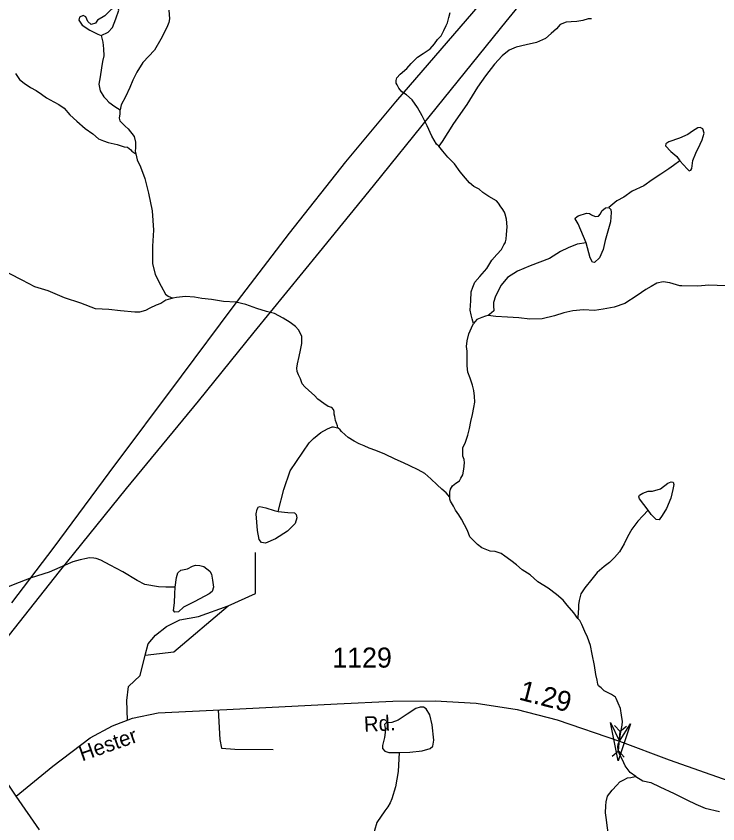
# Model space of a CAD drawing. Extents: x 2056842 to 2160602, y 826753 to 1016856.
# Drawn here: x 2087343 to 2091724, y 880850 to 885889 of the extents above; entities that cross this region are included whole.
import ezdxf

# ---------------------------------------------------------------- set-up
doc = ezdxf.new("R2010")
doc.units = 0
for name, color, linetype in [('Exist Hydrographic Creek Single Shore', 7, 'Continuous'), ('Exist Hydrographic Misc Water Feature', 7, 'Continuous'), ('Exist Road Non-System Type 51', 7, 'Continuous'), ('Exist Road Primary Interstate Divided Center Attributed', 7, 'Continuous'), ('Exist Road Secondary Mileage Hundredths English Label', 7, 'Continuous'), ('Exist Road Secondary Structure Pipe Attributed CELL', 7, 'Continuous'), ('Exist Road Secondary Structure Pipe CELL', 7, 'Continuous'), ('Exist Road Secondary Type 51 Attributed', 7, 'Continuous'), ('Exist Road Secondary Type 51 Label', 7, 'Continuous'), ('Exist Road Secondary Type 51 Number Label', 7, 'Continuous')]:
    doc.layers.add(name, color=color, linetype=linetype)

msp = doc.modelspace()

# ---------------------------------------------------------------- linework, layer by layer
at = {"layer": 'Exist Hydrographic Creek Single Shore'}
for points in [[(2088296.1, 885925.2), (2088300.2, 885873), (2088296.1, 885849.3), (2088288.1, 885829.4), (2088268.3, 885789), (2088246.5, 885745.2), (2088206.7, 885677), (2088133.3, 885600.5), (2088095.4, 885538.4), (2088071.6, 885490.5), (2088051.5, 885444.4), (2088025.7, 885386.3), (2087997.8, 885336.2), (2087991.6, 885304.2)], [(2089982.1, 885078.3), (2089966.3, 885090.4), (2089938.1, 885140.2), (2089908, 885204.1), (2089877.7, 885266.1), (2089847.7, 885319.9), (2089815.5, 885365.8), (2089779.4, 885397.8), (2089751.3, 885417.7), (2089731.1, 885439.4), (2089721, 885459.7), (2089715, 885471.6), (2089715, 885487.4), (2089718.9, 885503.7), (2089740.8, 885527.5), (2089780.8, 885561.8), (2089808.7, 885593.7), (2089848.6, 885633.9), (2089884.5, 885656.1), (2089928.4, 885684.1), (2089954.3, 885716.4), (2089972.3, 885742.2), (2089996, 885766.4), (2090012.1, 885798.5), (2090027.9, 885830.3), (2090035.8, 885846.6), (2090043.7, 885880.5), (2090051.6, 885912.5)], [(2087874.3, 885768.4), (2087884.8, 885725.8), (2087886.9, 885685.7), (2087889.1, 885642), (2087881.3, 885605.8), (2087875, 885565.7), (2087867.6, 885510), (2087859.4, 885463.8), (2087867.8, 885422), (2087889.7, 885385.8), (2087903.9, 885371.8), (2087921.9, 885352.1), (2087958, 885324.3), (2087991.6, 885304.2)], [(2087339.2, 885530.1), (2087363.4, 885494.4), (2087391.7, 885470.3), (2087431.6, 885444.7), (2087467.7, 885424.6), (2087499.9, 885402.7), (2087531.9, 885378.7), (2087577.6, 885354.8), (2087610, 885336.9), (2087642.2, 885315.3), (2087678.1, 885273.4), (2087722.4, 885233.4), (2087774.3, 885187.4), (2087820.4, 885153.7), (2087856.7, 885123.8), (2087888.5, 885110.1), (2087916.6, 885100.1), (2087972.8, 885088.4), (2088016.7, 885074.4), (2088037, 885070.5), (2088058.9, 885054.6), (2088064.8, 885046.4), (2088088.8, 885030.5)], [(2087991.6, 885304.2), (2087990.2, 885300.4), (2087989.8, 885280.1), (2087986.1, 885252.3), (2087990.2, 885236.3), (2088004.1, 885220.3), (2088022.4, 885202.6), (2088042.3, 885186.6), (2088078.4, 885138.5), (2088088.6, 885102.4), (2088088.6, 885082.5), (2088088.6, 885066.7), (2088084.7, 885046.6), (2088088.8, 885030.5)], [(2090197.8, 883971.3), (2090189.5, 884001), (2090183.5, 884025.1), (2090177.5, 884055.1), (2090181.4, 884113.1), (2090183.2, 884169.2), (2090192.9, 884197.2), (2090207, 884229), (2090238.6, 884265.1), (2090280.7, 884315.4), (2090312.6, 884365.6), (2090344.5, 884401.7), (2090372.4, 884433.6), (2090388.1, 884461.9), (2090396.2, 884473.8), (2090398, 884481.7), (2090401.9, 884497.7), (2090403.8, 884525.8), (2090407.8, 884573.7), (2090403.5, 884621.7), (2090395.6, 884653.7), (2090391.6, 884665.9), (2090377.4, 884689.8), (2090369.4, 884699.8), (2090353.4, 884721.5), (2090341.3, 884737.5), (2090293.2, 884763.4), (2090257, 884789.4), (2090233.2, 884809.3), (2090201, 884827), (2090172.9, 884848.9), (2090149, 884878.9), (2090114.6, 884916.7), (2090078.6, 884966.7), (2090038.4, 885008.5), (2090006.4, 885046.6), (2089982.1, 885078.3)], [(2088088.8, 885030.5), (2088098.7, 884992.6), (2088119, 884948.9), (2088145.2, 884876.7), (2088169.6, 884785), (2088192, 884674.9), (2088200.2, 884553.2), (2088194.6, 884452.9), (2088193.2, 884345.2), (2088211.3, 884277.2), (2088247.1, 884205.1), (2088275.6, 884153.3), (2088291.8, 884141.1), (2088321.8, 884129.3)], [(2090902.2, 884475.4), (2090844.3, 884467.1), (2090788.3, 884443.2), (2090740.6, 884420.8), (2090672.5, 884376.8), (2090552.9, 884330.4), (2090472.8, 884298.3), (2090410.8, 884258.2), (2090370.9, 884209.8), (2090335.4, 884141.8), (2090323.7, 884101.7), (2090323.7, 884081.9), (2090325.5, 884050), (2090309.5, 884037.8), (2090289.5, 884021.8)], [(2088321.3, 884129.2), (2088277.4, 884117), (2088245.5, 884097), (2088217.7, 884085.1), (2088177.6, 884066.9), (2088149.8, 884052.7), (2088111.8, 884042.7), (2088083.6, 884042.6), (2087993.9, 884050.3), (2087921.8, 884058.1), (2087837.6, 884063.7), (2087745.5, 884097.5), (2087643.5, 884131.1), (2087543.3, 884174.8), (2087459.2, 884200.5), (2087379.3, 884242.2), (2087303.1, 884282.2), (2087247.2, 884307.9), (2087207.1, 884323.8)], [(2091771, 884206.2), (2091667, 884209.8), (2091598.7, 884203.4), (2091498.9, 884205.3), (2091487, 884205.4), (2091423.2, 884225.3), (2091382.8, 884230.9), (2091342.8, 884222.8), (2091307.1, 884202.6), (2091274.9, 884182.7), (2091219.2, 884146.5), (2091143.3, 884096.4), (2091075.4, 884072.2), (2091007.5, 884059.8), (2090953.6, 884051.7), (2090885.3, 884055.6), (2090817.5, 884051.3), (2090761.5, 884037), (2090703.7, 884019), (2090625.9, 884000.8), (2090549.5, 883998.6), (2090481.4, 884006), (2090409.4, 884010.1), (2090337.8, 884015.6), (2090289.5, 884021.8)], [(2089351.9, 883320.8), (2089347.9, 883332.7), (2089335.8, 883366.7), (2089331.7, 883390.4), (2089327.4, 883406.6), (2089327.4, 883422.7), (2089323.4, 883434.5), (2089313.5, 883446.6), (2089291.3, 883454.2), (2089263.5, 883472.2), (2089225.3, 883498.3), (2089205.1, 883522), (2089169.1, 883553.9), (2089145.2, 883576), (2089128.9, 883595.7), (2089117.1, 883625.8), (2089104.8, 883651.7), (2089096.7, 883671.9), (2089094.8, 883691.6), (2089098.7, 883719.7), (2089110.4, 883765.8), (2089118.5, 883805.9), (2089126.2, 883845.8), (2089126.1, 883889.8), (2089118, 883909.6), (2089106, 883931.9), (2089087.7, 883953.6), (2089053.8, 883977.6), (2089009.7, 884005.4), (2088955.5, 884033.4), (2088905.6, 884047.2), (2088845.6, 884064.9), (2088777.6, 884090.6), (2088713.5, 884104.4), (2088637.5, 884108.2), (2088561.3, 884122), (2088501.4, 884127.8), (2088455.3, 884135.6), (2088399.3, 884139.4), (2088343.4, 884133.3), (2088321.3, 884129.2)], [(2090289.5, 884021.8), (2090273.5, 884017.7), (2090250.1, 884009.5), (2090217.9, 883997.3), (2090197.8, 883971.5)], [(2090051, 882887), (2090050.9, 882898.8), (2090051, 882918.8), (2090055, 882938.7), (2090066.9, 882958.8), (2090086.9, 882974.8), (2090110.9, 882989.1), (2090118.8, 883007), (2090130.7, 883027.1), (2090136.7, 883063), (2090142.4, 883103), (2090140.2, 883123), (2090132.4, 883143.2), (2090132.3, 883171.1), (2090132.2, 883195), (2090148, 883231.1), (2090161.7, 883275.1), (2090173.7, 883315.3), (2090181.5, 883359.1), (2090191.6, 883403.2), (2090199.4, 883447.3), (2090205.4, 883481.3), (2090205.1, 883517.4), (2090200.9, 883553.2), (2090192.8, 883587.2), (2090176.6, 883631.2), (2090162.6, 883667.2), (2090158.5, 883707), (2090158.4, 883747), (2090158.2, 883787.1), (2090158.1, 883799.2), (2090154.1, 883827.2), (2090158.1, 883863.2), (2090167.9, 883907), (2090185.7, 883945), (2090197.8, 883971.3)], [(2090051, 882887), (2090027, 882914.7), (2090000.9, 882938.5), (2089970.9, 882964.4), (2089930.7, 883002.3), (2089894.6, 883036.2), (2089852.7, 883058.1), (2089800.5, 883084.1), (2089760.5, 883102), (2089708.5, 883125.7), (2089644.4, 883155.6), (2089588.2, 883179.4), (2089546.1, 883193.4), (2089516.2, 883207.1), (2089484, 883220.9), (2089452.2, 883237), (2089416, 883260.7), (2089395.9, 883276.9), (2089374, 883296.7), (2089365.8, 883308.7), (2089351.9, 883320.8)], [(2090849.4, 882131.6), (2090825.2, 882165.2), (2090783.2, 882213.3), (2090756.9, 882245), (2090717, 882281), (2090664.7, 882320.8), (2090600.5, 882360.5), (2090552.5, 882402.5), (2090502.3, 882434.4), (2090466.2, 882466.3), (2090430.3, 882492), (2090394.2, 882519.9), (2090370.2, 882535.9), (2090334, 882547.8), (2090302, 882551.7), (2090250.2, 882571.5), (2090222.1, 882593.4), (2090175.8, 882639.3), (2090159.9, 882679.3), (2090123.6, 882750.9), (2090105.5, 882776.9), (2090085.4, 882806.9), (2090073.1, 882831.1), (2090055.1, 882862.9), (2090051.1, 882874.8), (2090051, 882887)], [(2088335.3, 882326.4), (2088276.6, 882326.4), (2088230.4, 882327.6), (2088145.2, 882343), (2088099.1, 882367), (2088008.9, 882422.5), (2087928.9, 882464.3), (2087870.9, 882494.1), (2087842.8, 882506.1), (2087827, 882508.2), (2087798.7, 882510), (2087782.7, 882505.9), (2087742.9, 882495.8), (2087696.6, 882483.7), (2087649, 882463.3), (2087549.1, 882419.2), (2087437.2, 882385), (2087361.3, 882356.3), (2087281.3, 882324.2)], [(2091212.2, 881144.6), (2091176.3, 881170.6), (2091146, 881212.6), (2091128.1, 881248.4), (2091110.1, 881284.2), (2091101.8, 881310.3), (2091099.2, 881329.6), (2091101.8, 881347.1), (2091108.6, 881364.6), (2091116.7, 881410.4), (2091127.3, 881464.3), (2091127.5, 881488.3), (2091123, 881528.4), (2091115, 881568.3), (2091100.9, 881602.4), (2091088.8, 881632.1), (2091085, 881640.1), (2091058.8, 881656.1), (2091014.6, 881679.9), (2090994.7, 881698.1), (2090978.5, 881709.9), (2090974.5, 881721.8), (2090970.7, 881745.8), (2090962.6, 881781.7), (2090954.2, 881837.7), (2090939.9, 881907.9), (2090927.9, 881961.6), (2090909.6, 882013.5), (2090893.6, 882049.6), (2090873.6, 882093.7), (2090861.3, 882117.5), (2090849.4, 882131.6)], [(2089734.8, 881295.2), (2089727.3, 881175.2), (2089711, 881079.9), (2089688.5, 881004.9), (2089678.5, 880981.2), (2089663.5, 880954.9), (2089645.4, 880929.9), (2089593.6, 880858.7), (2089579.8, 880807.4), (2089573.6, 880778.6), (2089568.3, 880749.7), (2089547.8, 880721.6), (2089502.1, 880671.6), (2089388.5, 880607.2), (2089350.3, 880587.1), (2089314.8, 880575.1), (2089278.8, 880562.6), (2089202.9, 880538.4), (2089142.8, 880512.3), (2088981.3, 880458.8)], [(2091003.6, 880736.2), (2091015.8, 880752), (2091021.7, 880770.3), (2091029.5, 880782.2), (2091037.6, 880794.2), (2091037.3, 880810.3), (2091033.3, 880838.3), (2091029.1, 880874.1), (2091021.2, 880918.2), (2091025, 880962.1), (2091026.8, 880986), (2091034.8, 881022), (2091064.8, 881060.1), (2091092.7, 881090.3), (2091112.5, 881112.2), (2091136.3, 881124.6), (2091160.5, 881136.5), (2091180.3, 881138.7), (2091208.3, 881144.7), (2091212.2, 881144.6)], [(2091212.2, 881144.6), (2091256.3, 881118.8), (2091304.6, 881107), (2091360.5, 881081.2), (2091450.6, 881039.3), (2091530.8, 880999.6), (2091587, 880971.9), (2091644.9, 880948), (2091733, 880926.2)]]:
    msp.add_lwpolyline(points, dxfattribs=at)
at = {"layer": 'Exist Hydrographic Misc Water Feature'}
for points in [[(2087874.3, 885768.4), (2087918.1, 885788.4), (2087944.3, 885818.4), (2087964.3, 885872.2), (2087983, 885927.2), (2087974.3, 885953.5), (2087955.5, 885954.7), (2087938.1, 885932.2), (2087896.8, 885891), (2087850.6, 885864.7), (2087838.1, 885844.7), (2087810.6, 885836), (2087790.6, 885856), (2087778.1, 885884.7), (2087760.6, 885892.2), (2087738.1, 885883.5), (2087733.1, 885863.5), (2087754.4, 885833.5), (2087803.1, 885802.2), (2087853.1, 885775.9), (2087874.3, 885768.4)], [(2090934.3, 885872.5), (2090913.6, 885871.6), (2090880.2, 885861.3), (2090843.7, 885855), (2090807.8, 885853.2), (2090776, 885850.7), (2090740, 885836.7), (2090716.2, 885810.6), (2090684, 885780.7), (2090648.5, 885748.7), (2090590.5, 885724.2), (2090526.5, 885710), (2090464.2, 885695.9), (2090420.5, 885675.7), (2090376.6, 885641.8), (2090328.8, 885589.4), (2090273.1, 885517.5), (2090223.2, 885445.1), (2090155.4, 885337), (2090074.1, 885218.6), (2090002.4, 885106.5), (2089982.3, 885078.7)], [(2091486.3, 884985.4), (2091531.6, 884936.1), (2091544.1, 884924.8), (2091554.1, 884928.6), (2091561.6, 884938.6), (2091566.6, 884987.3), (2091585.3, 885034.8), (2091614, 885091.1), (2091626.5, 885117.3), (2091639, 885158.6), (2091629, 885186.1), (2091614, 885194.9), (2091597.8, 885191.1), (2091565.3, 885172.3), (2091535.3, 885151.1), (2091484.1, 885127.3), (2091416.6, 885104.8), (2091399.1, 885092.3), (2091396.6, 885079.8), (2091430.4, 885044.8), (2091466.6, 885013.6), (2091486.3, 884985.4)], [(2091486.3, 884985.4), (2091446.8, 884956.9), (2091416.6, 884937.1), (2091366.8, 884902.9), (2091312.9, 884866.9), (2091260.8, 884830.5), (2091189.2, 884796.4), (2091137.3, 884760), (2091093, 884736.7), (2091043, 884694.1)], [(2090902.2, 884475.4), (2090851.9, 884592.9), (2090833.1, 884624.1), (2090834.4, 884631.6), (2090850.6, 884642.9), (2090904.3, 884660.4), (2090923.1, 884657.9), (2090934.3, 884649.1), (2090958.1, 884637.9), (2090978, 884641.6), (2090990.5, 884655.4), (2090999.3, 884674.1), (2091021.8, 884692.9), (2091043, 884694.1)], [(2091043, 884694.1), (2091055.5, 884682.9), (2091058, 884662.9), (2091053, 884606.6), (2091020.5, 884489.1), (2091008, 884432.9), (2090984.3, 884381.6), (2090953.1, 884351.6), (2090940.6, 884354.1), (2090925.6, 884380.3), (2090902.2, 884475.4)], [(2088977.6, 882799.3), (2089013.9, 882935.6), (2089053.8, 883053.1), (2089172.3, 883226.1), (2089200, 883254.4), (2089245.9, 883290.5), (2089286.1, 883314.3), (2089315.7, 883326.5), (2089323.9, 883326.5), (2089340.3, 883322.9), (2089351.8, 883320.7)], [(2091287.6, 882806.8), (2091234.2, 882876.9), (2091230.4, 882889.4), (2091234.2, 882899.4), (2091255.4, 882913.1), (2091289.2, 882924.4), (2091316.7, 882925.6), (2091366.6, 882940.6), (2091411.6, 882975.6), (2091432.9, 882984.4), (2091445.4, 882980.6), (2091449.1, 882966.9), (2091442.9, 882935.6), (2091429.1, 882881.9), (2091404.1, 882818.1), (2091376.6, 882774.3), (2091356.6, 882746.8), (2091339.1, 882749.3), (2091306.7, 882780.6), (2091287.6, 882806.8)], [(2088977.6, 882799.3), (2089038.9, 882793.1), (2089080.1, 882789.3), (2089090.1, 882779.3), (2089095.1, 882758.1), (2089085.1, 882723.1), (2089037.6, 882675.6), (2088961.4, 882628.1), (2088898.9, 882601.8), (2088873.9, 882605.6), (2088858.9, 882624.3), (2088850.2, 882679.3), (2088840.2, 882783.1), (2088847.7, 882811.9), (2088856.4, 882828.1), (2088863.9, 882830.6), (2088901.4, 882820.6), (2088952.6, 882804.3), (2088977.6, 882799.3)], [(2091287.6, 882806.8), (2091255.7, 882770.7), (2091223.5, 882738.7), (2091187.6, 882688.5), (2091160.1, 882640.3), (2091138, 882596.7), (2091109.9, 882546.5), (2091078.3, 882512.4), (2091046.7, 882480.2), (2091014.7, 882454.3), (2090970.8, 882417.9), (2090936.6, 882375.9), (2090892.7, 882321.8), (2090868.9, 882285.6), (2090857.2, 882243.6), (2090853.6, 882215.7), (2090853.6, 882195.5), (2090849.2, 882139.7), (2090849.7, 882131.5)], [(2088335.3, 882326.4), (2088342.8, 882387.6), (2088352.8, 882415.1), (2088371.6, 882431.4), (2088412.8, 882441.4), (2088442.8, 882457.7), (2088462.8, 882463.9), (2088489, 882461.4), (2088515.3, 882455.2), (2088552.8, 882426.4), (2088562.8, 882407.6), (2088567.8, 882370.1), (2088575.2, 882326.4), (2088566.5, 882300.1), (2088547.8, 882285.1), (2088459, 882236.4), (2088387.8, 882201.4), (2088355.3, 882171.4), (2088334.1, 882170.1), (2088325.4, 882181.4), (2088330.4, 882228.9), (2088332.8, 882283.9), (2088335.3, 882326.4)], [(2089734.8, 881295.2), (2089799.7, 881296.5), (2089878.4, 881305.2), (2089928.4, 881319), (2089944.7, 881334), (2089950.9, 881372.7), (2089939.7, 881466.5), (2089925.9, 881529), (2089903.4, 881566.5), (2089885.9, 881577.8), (2089866, 881577.8), (2089837.2, 881569), (2089784.7, 881534), (2089727.3, 881496.5), (2089688.5, 881482.8), (2089652.3, 881479), (2089642.3, 881470.3), (2089643.5, 881457.7), (2089648.5, 881436.5), (2089642.3, 881387.7), (2089629.8, 881339), (2089629.8, 881319), (2089643.5, 881302.7), (2089669.8, 881295.2), (2089734.8, 881295.2)]]:
    msp.add_lwpolyline(points, dxfattribs=at)
at = {"layer": 'Exist Road Non-System Type 51'}
for points in [[(2088666.1, 882208.8), (2088837.2, 882286.8), (2088837.2, 882541.6)], [(2088148.3, 881901.7), (2088326.9, 881922.6), (2088666.1, 882208.8)], [(2088148.3, 881901.7), (2088166.4, 881973), (2088212, 882026.3), (2088282.3, 882081.4), (2088364, 882123.2), (2088481.8, 882144.1), (2088666.1, 882208.8)], [(2088036.8, 881496.8), (2088034.3, 881618.4), (2088043.8, 881705.8), (2088117.9, 881776.2), (2088148.3, 881901.7)], [(2088603.1, 881560.2), (2088613.9, 881375), (2088625.3, 881321.7), (2088707, 881316), (2088946.4, 881314.1)]]:
    msp.add_lwpolyline(points, dxfattribs=at)
at = {"layer": 'Exist Road Primary Interstate Divided Center Attributed'}
for points in [[(2093603.5, 890839.4), (2093321.9, 890160.7), (2093122.2, 889678.2), (2093003.4, 889422.6), (2092897.2, 889219.2), (2092773, 888995.9), (2092636.3, 888779.9), (2092495, 888585.5), (2092347.5, 888387.4), (2092149.5, 888155.2), (2091410.1, 887297.4), (2091141.1, 886996.7), (2090747.9, 886546.6), (2090236.9, 885963.4), (2089711.4, 885354.9), (2089398.3, 884980.4), (2089047.4, 884535.7), (2088695.6, 884074.9), (2088373.5, 883642.8), (2087920.9, 883039.7), (2087578.1, 882575.2), (2087312.7, 882227.8)], [(2087204.7, 881910.9), (2087614.1, 882424), (2088032.5, 882942.5), (2088481.4, 883486.2), (2088828.7, 883918.2), (2089236.3, 884416.9), (2089574.6, 884831), (2089929.1, 885272), (2090402.4, 885855.3), (2090859.5, 886417), (2091276.1, 886928.3), (2091575.7, 887299.2), (2092172.9, 888029.2), (2092333.1, 888229), (2092531, 888481), (2092706.5, 888724.1), (2092848.6, 888952.7), (2092962, 889150.7), (2093075.4, 889366.8), (2093183.3, 889599), (2093399.3, 890112.1), (2093661.1, 890749.4)]]:
    msp.add_lwpolyline(points, dxfattribs=at)
at = {"layer": 'Exist Road Secondary Structure Pipe Attributed CELL'}
msp.add_lwpolyline([(2091179.2, 881473.7), (2091100.4, 881242.9), (2091053.2, 881482.2), (2091108.6, 881364.6)], close=True, dxfattribs=at)
at = {"layer": 'Exist Road Secondary Structure Pipe CELL'}
for p, q in [((2091078.9, 881462.5), (2091113.1, 881424.9)), ((2091152.4, 881457), (2091113.1, 881424.9)), ((2091104.1, 881304.3), (2091113.1, 881424.9)), ((2091064.7, 881272.2), (2091104.1, 881304.3)), ((2091138.2, 881266.7), (2091104.1, 881304.3))]:
    msp.add_line(p, q, dxfattribs=at)
at = {"layer": 'Exist Road Secondary Type 51 Attributed'}
for points in [[(2087343.7, 881023.3), (2087572.3, 881210.4), (2087804.7, 881386.3), (2087943.2, 881460.8), (2088069.1, 881509.3), (2088230, 881542.1), (2088659, 881562.9), (2089346.5, 881599.4), (2089695, 881615.8), (2089959.5, 881618.1), (2090215.7, 881603.2), (2090470.4, 881562.9), (2090721.4, 881498.1), (2091108.6, 881364.6), (2091419.3, 881249.9), (2091792.5, 881118), (2092111.2, 881040.5), (2092381.6, 881017.3), (2092724.2, 881012.9), (2093040, 881045.7), (2093348.4, 881117.2), (2093538.3, 881153.7), (2093708.1, 881180.6), (2093893.2, 881196.6)], [(2087343.7, 881023.3), (2087059.9, 881439.9), (2086966.9, 881577.7)], [(2087488.2, 880813.1), (2087343.7, 881023.3)]]:
    msp.add_lwpolyline(points, dxfattribs=at)

# ---------------------------------------------------------------- texts
at = {"layer": 'Exist Road Secondary Mileage Hundredths English Label'}
msp.add_text('1.29', height=125, rotation=345.5151, dxfattribs=at).set_placement((2090475.6, 881626.1))
at = {"layer": 'Exist Road Secondary Type 51 Label'}
for s, rotation, p in [('Rd.', 3.1509, (2089516.2, 881423.4)), ('Hester', 19.3715, (2087754.7, 881238.7))]:
    msp.add_text(s, height=95, rotation=rotation, dxfattribs=at).set_placement(p)
at = {"layer": 'Exist Road Secondary Type 51 Number Label'}
msp.add_text('1129', height=125, dxfattribs=at).set_placement((2089316.4, 881824.4))

doc.saveas('drawing.dxf')
